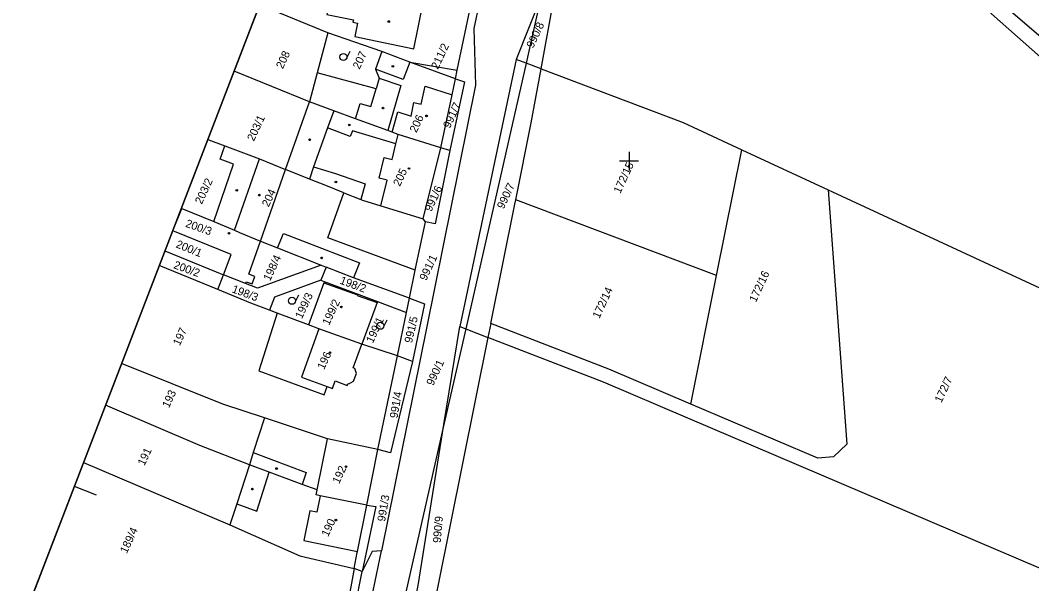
# Model space of a CAD drawing. Extents: x -755344 to -754413, y -1162670 to -1161477.
# Drawn here: x -755129.3 to -754914.5, y -1161889.7 to -1161770.1 of the extents above; entities that cross this region are included whole.
import ezdxf

# ---------------------------------------------------------------- set-up
doc = ezdxf.new("R2010")
doc.units = 0
for name, color, linetype in [('Formát', 7, 'Continuous'), ('Síť', 7, 'Continuous'), ('Vrstva 55', 7, 'Continuous'), ('Vrstva 56', 7, 'Continuous'), ('Vrstva 57', 7, 'Continuous'), ('Vrstva 58', 7, 'Continuous'), ('Vrstva 59', 7, 'Continuous')]:
    doc.layers.add(name, color=color, linetype=linetype)

msp = doc.modelspace()

# ---------------------------------------------------------------- linework, layer by layer
at = {"layer": 'Formát'}
for p, q in [((-755042.37, -1161673.02), (-755344.08, -1162456.97)), ((-755042.37, -1161673.02), (-755344.08, -1162456.97)), ((-755117.8, -1161869.01), (-755113.13, -1161870.81))]:
    msp.add_line(p, q, dxfattribs=at)
msp.add_lwpolyline([(-754488.01, -1161886.37), (-754789.71, -1162670.32), (-755344.08, -1162456.97), (-755042.37, -1161673.02)], close=True, dxfattribs=at)
msp.add_lwpolyline([(-754789.71, -1162670.32), (-754488.01, -1161886.37), (-755042.37, -1161673.02), (-755344.08, -1162456.97)], dxfattribs=at)
at = {"layer": 'Síť'}
for points in [[(-755000, -1161798), (-755000, -1161800), (-755000, -1161802)], [(-754998, -1161800), (-755000, -1161800), (-755002, -1161800)]]:
    msp.add_lwpolyline(points, dxfattribs=at)
at = {"layer": 'Vrstva 55'}
for p, q in [((-755036.5, -1161780.73), (-755029.37, -1161746.66)), ((-755018.69, -1161780.44), (-755012.38, -1161745.91)), ((-755018.66, -1161765.05), (-755023.99, -1161778.44)), ((-755063.99, -1161772.75), (-755078.47, -1161766.81)), ((-755063.99, -1161772.75), (-755066.23, -1161781.24)), ((-755052.51, -1161776.75), (-755063.99, -1161772.75)), ((-755046.56, -1161779), (-755052.51, -1161776.75)), ((-755036.87, -1161782.52), (-755046.56, -1161779)), ((-755046.56, -1161779), (-755036.5, -1161780.73)), ((-755023.99, -1161778.44), (-755035.96, -1161835.09)), ((-755067.86, -1161787.41), (-755083.88, -1161780.88)), ((-755066.23, -1161781.24), (-755067.86, -1161787.41)), ((-755036.87, -1161782.52), (-755036.5, -1161780.73)), ((-755072.94, -1161801.75), (-755067.86, -1161787.41)), ((-755038.07, -1161797.72), (-755039.95, -1161797.18)), ((-754981.41, -1161824.3), (-754976.02, -1161797.59)), ((-754976.02, -1161797.59), (-754957.73, -1161806.07)), ((-754981.41, -1161824.3), (-755024.07, -1161808.23)), ((-755095.09, -1161810.02), (-755094.97, -1161810.07)), ((-755094.97, -1161810.07), (-755088.17, -1161812.84)), ((-755045.44, -1161823.16), (-755043.26, -1161812.92)), ((-755098.56, -1161819.02), (-755086.12, -1161824.14)), ((-755087.3, -1161827.26), (-755099.76, -1161822.16)), ((-755064.35, -1161822.48), (-755065.45, -1161825.27)), ((-755065.41, -1161822.06), (-755064.35, -1161822.48)), ((-755087.3, -1161827.26), (-755086.12, -1161824.14)), ((-755081.43, -1161826), (-755086.12, -1161824.14)), ((-755046.61, -1161829.09), (-755045.44, -1161823.16)), ((-754986.91, -1161851.57), (-754981.41, -1161824.3)), ((-755065.45, -1161825.27), (-755064.74, -1161825.54)), ((-755064.74, -1161825.54), (-755053.39, -1161829.8)), ((-755053.39, -1161829.8), (-755047.24, -1161832.11)), ((-755047.24, -1161832.11), (-755046.61, -1161829.09)), ((-755074.72, -1161832.26), (-755076.34, -1161831.64)), ((-755068.04, -1161834.73), (-755074.72, -1161832.26)), ((-755049.18, -1161841.35), (-755047.24, -1161832.11)), ((-755029.36, -1161834.44), (-755029.96, -1161837.42)), ((-755049.18, -1161841.35), (-755056.74, -1161838.86)), ((-755053.32, -1161861.22), (-755049.18, -1161841.35)), ((-755046.01, -1161842.53), (-755049.18, -1161841.35)), ((-755055.68, -1161873.06), (-755053.32, -1161861.22)), ((-755058.39, -1161886.49), (-755064.41, -1161919.47)), ((-755056.71, -1161887.12), (-755058.39, -1161886.49)), ((-755077.79, -1161993.12), (-755056.71, -1161887.12))]:
    msp.add_line(p, q, dxfattribs=at)
for points in [[(-755013.38, -1161684.18), (-755015.84, -1161699.17), (-755023.66, -1161739.37), (-755030.54, -1161760.43), (-755032.94, -1161771.83), (-755032.59, -1161783.86), (-755042.91, -1161835.1), (-755052.57, -1161882.7), (-755054.53, -1161882.87), (-755056.71, -1161887.12)], [(-754790.69, -1161920.17), (-754823.33, -1161865.1), (-754831.37, -1161854.01), (-754842.43, -1161841.79), (-754855.01, -1161828.87), (-754953.69, -1161741.58)], [(-755066.7, -1161752.01), (-755068.08, -1161759.03), (-755062.31, -1161760.06), (-755064.15, -1161768.86), (-755058.51, -1161770.01), (-755058.63, -1161770.54), (-755057.66, -1161770.75), (-755058.23, -1161773.52), (-755045.73, -1161776.2), (-755043.71, -1161766.41), (-755042.79, -1161761.96), (-755039.2, -1161744.67), (-755029.37, -1161746.66)], [(-755052.51, -1161776.75), (-755053.85, -1161780.46), (-755053.05, -1161782.42), (-755053.71, -1161784.66), (-755066.23, -1161781.24)], [(-755018.69, -1161780.44), (-755021.88, -1161779.23), (-755023.99, -1161778.44)], [(-755024.07, -1161808.23), (-755020.78, -1161791.91), (-755018.69, -1161780.44)], [(-755018.69, -1161780.44), (-754988.48, -1161791.81), (-754976.02, -1161797.59)], [(-755039.95, -1161797.18), (-755037.58, -1161785.91), (-755036.87, -1161782.52)], [(-755036.87, -1161782.52), (-755034.91, -1161783.19), (-755038.07, -1161797.72)], [(-755039.95, -1161797.18), (-755049.05, -1161794.33), (-755050.33, -1161793.86), (-755051.25, -1161793.52), (-755058.07, -1161791.01), (-755062.7, -1161789.31), (-755067.86, -1161787.41)], [(-755089.48, -1161795.42), (-755085.83, -1161796.77)], [(-755088.17, -1161812.84), (-755084.01, -1161800.63), (-755086.86, -1161799.58), (-755085.83, -1161796.77)], [(-755085.83, -1161796.77), (-755078.48, -1161799.49), (-755072.94, -1161801.75)], [(-755043.26, -1161812.92), (-755043.71, -1161812.24), (-755039.95, -1161797.18)], [(-755038.07, -1161797.72), (-755041.18, -1161813.33), (-755043.26, -1161812.92)], [(-755045.44, -1161823.16), (-755064, -1161816.28), (-755060.56, -1161806.72), (-755064.4, -1161805.16), (-755067.84, -1161803.8), (-755072.94, -1161801.75)], [(-754957.73, -1161806.07), (-754898.34, -1161833.59), (-754912.51, -1161886.53), (-754987.52, -1161854.57), (-755005.46, -1161846.93), (-755029.96, -1161837.42)], [(-754957.73, -1161806.07), (-754953.79, -1161860.09), (-754956.58, -1161862.75), (-754959.95, -1161863.06), (-754986.91, -1161851.57)], [(-755029.36, -1161834.44), (-755024.25, -1161809.12), (-755024.07, -1161808.23)], [(-755086.12, -1161824.14), (-755084.49, -1161819.84), (-755096.9, -1161814.81), (-755094.97, -1161810.07)], [(-755088.17, -1161812.84), (-755083.75, -1161814.68), (-755082.7, -1161815.12), (-755078.25, -1161816.98)], [(-755081.43, -1161826), (-755081.29, -1161825.61), (-755080, -1161826.07), (-755079.47, -1161824.46), (-755080.73, -1161824.02), (-755078.25, -1161816.98)], [(-755078.25, -1161816.98), (-755074.63, -1161818.41), (-755065.41, -1161822.06)], [(-755065.41, -1161822.06), (-755078.92, -1161826.99), (-755081.43, -1161826)], [(-755046.61, -1161829.09), (-755058.54, -1161824.78), (-755064.35, -1161822.48)], [(-755065.45, -1161825.27), (-755075.27, -1161828.85), (-755076.34, -1161831.64)], [(-755064.74, -1161825.54), (-755064.84, -1161825.82), (-755068.04, -1161834.73)], [(-755076.34, -1161831.64), (-755080.31, -1161830.13), (-755087.3, -1161827.26)], [(-755053.39, -1161829.8), (-755053.47, -1161830.02), (-755056.74, -1161838.86)], [(-755046.61, -1161829.09), (-755043.45, -1161830.32), (-755046.01, -1161842.53)], [(-755074.72, -1161832.26), (-755078.65, -1161844.52), (-755064.76, -1161849.59), (-755064.08, -1161847.84), (-755062.95, -1161848.24), (-755062.42, -1161846.64), (-755059.89, -1161847.61), (-755059.74, -1161847.19), (-755059.5, -1161847.27), (-755058.48, -1161846.72), (-755057.9, -1161845.09), (-755058.26, -1161844), (-755058.56, -1161843.89), (-755056.74, -1161838.86)], [(-755056.74, -1161838.86), (-755065.91, -1161835.63), (-755068.04, -1161834.73)], [(-755053.45, -1161933.51), (-755044.81, -1161890.11), (-755039.31, -1161855.89), (-755035.96, -1161835.09)], [(-755035.96, -1161835.09), (-755034.69, -1161835.58), (-755029.96, -1161837.42)], [(-754986.91, -1161851.57), (-755004.33, -1161844.15), (-755029.36, -1161834.44)], [(-755029.96, -1161837.42), (-755040.69, -1161890.6), (-755049.81, -1161934.92)], [(-755077.38, -1161854.48), (-755086.27, -1161851.57), (-755107.78, -1161842.98)], [(-755046.01, -1161842.53), (-755050.67, -1161861.93), (-755053.32, -1161861.22)], [(-755080.57, -1161864.47), (-755091.15, -1161860.37), (-755111.17, -1161851.79)], [(-755077.38, -1161854.48), (-755079.84, -1161861.83), (-755080.57, -1161864.47)], [(-755053.32, -1161861.22), (-755064.04, -1161858.98), (-755077.38, -1161854.48)], [(-755115.84, -1161863.94), (-755084.79, -1161877.24)], [(-755080.57, -1161864.47), (-755083.3, -1161872.73), (-755084.79, -1161877.24)], [(-755055.68, -1161873.06), (-755065.57, -1161871.04), (-755066.47, -1161870.86), (-755066.22, -1161869.81), (-755069.39, -1161868.63), (-755076.39, -1161866.02), (-755080.57, -1161864.47)], [(-755058.39, -1161886.49), (-755057.71, -1161883.06), (-755057.66, -1161882.87), (-755055.68, -1161873.06)], [(-755055.68, -1161873.06), (-755053.78, -1161873.28), (-755056.71, -1161887.12)], [(-755084.79, -1161877.24), (-755069.89, -1161883.79), (-755058.39, -1161886.49)]]:
    msp.add_lwpolyline(points, dxfattribs=at)
at = {"layer": 'Vrstva 56'}
for p, q in [((-754908.58, -1161777.13), (-754931.36, -1161757.54)), ((-755018.66, -1161765.05), (-755021.88, -1161779.23)), ((-755046.56, -1161779), (-755047.94, -1161782.68)), ((-755021.88, -1161779.23), (-755034.69, -1161835.58)), ((-755047.94, -1161782.68), (-755053.85, -1161780.46)), ((-755053.05, -1161782.42), (-755048.44, -1161783.92)), ((-755048.44, -1161783.92), (-755051.25, -1161793.52)), ((-755054.84, -1161788.43), (-755053.71, -1161784.66)), ((-755044.13, -1161787.9), (-755043.32, -1161784.1)), ((-755043.32, -1161784.1), (-755037.58, -1161785.91)), ((-755058.07, -1161791.01), (-755057.11, -1161787.75)), ((-755057.11, -1161787.75), (-755054.84, -1161788.43)), ((-755046.28, -1161790.43), (-755045.67, -1161787.57)), ((-755045.67, -1161787.57), (-755044.13, -1161787.9)), ((-755062.7, -1161789.31), (-755064.01, -1161792.95)), ((-755050.33, -1161793.86), (-755049.11, -1161789.56)), ((-755049.11, -1161789.56), (-755046.28, -1161790.43)), ((-755064.01, -1161792.95), (-755066.99, -1161801.2)), ((-755059.19, -1161794.76), (-755064.01, -1161792.95)), ((-755058.74, -1161793.58), (-755059.19, -1161794.76)), ((-755049.52, -1161796.33), (-755058.74, -1161793.58)), ((-755049.52, -1161796.33), (-755049.05, -1161794.33)), ((-755050.32, -1161799.64), (-755049.52, -1161796.33)), ((-755083.75, -1161814.68), (-755078.48, -1161799.49)), ((-755053.09, -1161803.64), (-755052.02, -1161799.21)), ((-755052.02, -1161799.21), (-755050.32, -1161799.64)), ((-755078.25, -1161816.98), (-755072.94, -1161801.75)), ((-755066.99, -1161801.2), (-755067.84, -1161803.8)), ((-755066.99, -1161801.2), (-755062.31, -1161802.61)), ((-755062.31, -1161802.61), (-755056.07, -1161804.84)), ((-755056.07, -1161804.84), (-755056.99, -1161808.17)), ((-755051.39, -1161804.05), (-755053.09, -1161803.64)), ((-755052.72, -1161809.52), (-755051.39, -1161804.05)), ((-755060.56, -1161806.72), (-755056.99, -1161808.17)), ((-755056.99, -1161808.17), (-755056.63, -1161808.32)), ((-755056.63, -1161808.32), (-755052.72, -1161809.52)), ((-755052.72, -1161809.52), (-755043.71, -1161812.24)), ((-755074.63, -1161818.41), (-755073.38, -1161815.35)), ((-755073.38, -1161815.35), (-755057.25, -1161821.58)), ((-755057.25, -1161821.58), (-755058.54, -1161824.78)), ((-755064.84, -1161825.82), (-755057.65, -1161828.38)), ((-755057.65, -1161828.38), (-755057.71, -1161828.5)), ((-755057.71, -1161828.5), (-755053.47, -1161830.02)), ((-755065.91, -1161835.63), (-755069.59, -1161845.88)), ((-755034.69, -1161835.58), (-755039.31, -1161855.89)), ((-755069.59, -1161845.88), (-755064.08, -1161847.84)), ((-755039.31, -1161855.89), (-755061.51, -1161953.6)), ((-755066.22, -1161869.81), (-755064.04, -1161858.98)), ((-755079.84, -1161861.83), (-755068.56, -1161866.07)), ((-755079.03, -1161874.3), (-755076.39, -1161866.02)), ((-755068.56, -1161866.07), (-755069.39, -1161868.63)), ((-755065.57, -1161871.04), (-755066.27, -1161874.54)), ((-755083.3, -1161872.73), (-755079.03, -1161874.3)), ((-755067.79, -1161874.23), (-755069.06, -1161880.5)), ((-755066.27, -1161874.54), (-755067.79, -1161874.23)), ((-755069.06, -1161880.5), (-755057.66, -1161882.87)), ((-755067.04, -1161952.84), (-755052.57, -1161882.7))]:
    msp.add_line(p, q, dxfattribs=at)
at = {"layer": 'Vrstva 58'}
for p, q in [((-755059.97, -1161778.21), (-755059.23, -1161776.63)), ((-755070.89, -1161829.96), (-755070.15, -1161828.38)), ((-755052.13, -1161835.26), (-755051.39, -1161833.68))]:
    msp.add_line(p, q, dxfattribs=at)
for centre in [(-755060.65, -1161777.9), (-755071.57, -1161829.65), (-755052.81, -1161834.95)]:
    msp.add_circle(centre, 0.75, dxfattribs=at)
at = {"layer": 'Vrstva 59'}
for centre in [(-755051.02, -1161770.37), (-755050.16, -1161779.87), (-755052.24, -1161788.75), (-755043.01, -1161790.4), (-755059.4, -1161792.33), (-755067.84, -1161795.48), (-755046.73, -1161801.57), (-755062.26, -1161804.43), (-755083.3, -1161806.22), (-755078.51, -1161807.22), (-755084.96, -1161815.31), (-755065.27, -1161820.54), (-755061.09, -1161830.96), (-755063.51, -1161840.65), (-755074.85, -1161865.26), (-755060.12, -1161864.87), (-755079.98, -1161869.62), (-755062.25, -1161876.21)]:
    msp.add_circle(centre, 0.175, dxfattribs=at)

# ---------------------------------------------------------------- texts
at = {"layer": 'Vrstva 57'}
for s, rotation, p in [('990/8', 65, (-755020.36, -1161776.16)), ('211/2', 65, (-755040.58, -1161780.65)), ('208', 65, (-755073.53, -1161780.54)), ('207', 65, (-755057.24, -1161780.64)), ('991/7', 65, (-755038.05, -1161793.18)), ('206', 65, (-755045.15, -1161794.1)), ('203/1', 65, (-755079.67, -1161795.9)), ('172/15', 65, (-755001.87, -1161807.01)), ('205', 65, (-755048.66, -1161805.49)), ('203/2', 65, (-755090.74, -1161809.29)), ('991/6', 65, (-755041.99, -1161810.86)), ('990/7', 65, (-755026.62, -1161810.3)), ('204', 65, (-755076.53, -1161809.86)), ('200/3', 340.5336, (-755094.33, -1161813.9)), ('200/1', 337.6705, (-755096.37, -1161818.26)), ('198/4', 65, (-755076.22, -1161825.58)), ('991/1', 65, (-755043.08, -1161825.51)), ('200/2', 340, (-755096.85, -1161822.7)), ('198/2', 339.5705, (-755061.56, -1161825.97)), ('172/16', 65, (-754973.07, -1161830.1)), ('198/3', 339.6039, (-755084.47, -1161827.81)), ('172/14', 65, (-755006.33, -1161833.55)), ('199/3', 65, (-755069.48, -1161833.6)), ('199/2', 65, (-755063.71, -1161834.99)), ('991/5', 77.0202, (-755046.1, -1161838.73)), ('197', 65, (-755095.42, -1161839.32)), ('199/1', 65, (-755054.41, -1161838.77)), ('196', 65, (-755064.77, -1161844.39)), ('990/1', 65, (-755041.6, -1161847.81)), ('172/7', 65, (-754933.68, -1161851.42)), ('193', 65, (-755097.71, -1161852.52)), ('991/4', 80.3171, (-755049.19, -1161854.68)), ('191', 65, (-755102.91, -1161864.78)), ('192', 65, (-755061.57, -1161868.62)), ('991/3', 80.3378, (-755051.82, -1161876.6)), ('190', 65, (-755063.9, -1161879.86)), ('990/9', 84.9969, (-755040, -1161881.1)), ('189/4', 65, (-755106.66, -1161883.41))]:
    msp.add_text(s, height=1.7, rotation=rotation, dxfattribs=at).set_placement(p)

doc.saveas('drawing.dxf')
